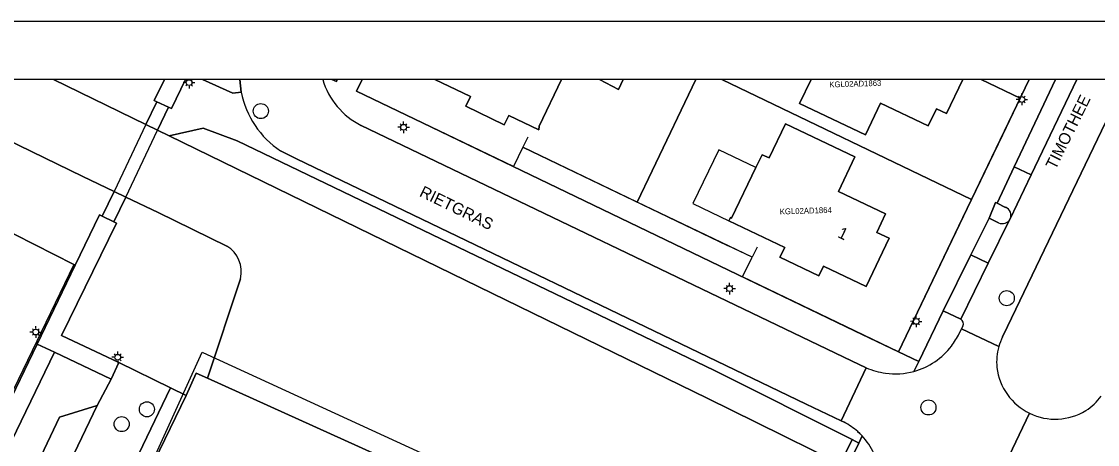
# Model space of a CAD drawing. Extents: x 124901 to 125496, y 515369 to 515789.
# Drawn here: x 125282.1 to 125375.1, y 515752.5 to 515789 of the extents above; entities that cross this region are included whole.
import ezdxf

# ---------------------------------------------------------------- set-up
doc = ezdxf.new("R2010")
doc.units = 0
for name, color, linetype in [('Alg Kaders', 7, 'Continuous'), ('Brug', 7, 'Continuous'), ('Gebouw', 7, 'Continuous'), ('Inrit', 7, 'Continuous'), ('Lichtmast', 7, 'Continuous'), ('Luifel', 7, 'Continuous'), ('Onbegroeid terrein', 7, 'Continuous'), ('Parkeren', 7, 'Continuous'), ('Perceelnummers', 7, 'Continuous'), ('Perceelsgrenzen', 7, 'Continuous'), ('Putten', 7, 'Continuous'), ('Scheiding', 7, 'Continuous'), ('Teksten', 7, 'Continuous'), ('Vegetatie', 7, 'Continuous'), ('Voetpad', 7, 'Continuous'), ('Water', 7, 'Continuous'), ('Wegen drempel verkeerseiland', 7, 'Continuous'), ('Wegen lokale weg', 7, 'Continuous')]:
    doc.layers.add(name, color=color, linetype=linetype)

msp = doc.modelspace()

# ---------------------------------------------------------------- linework, layer by layer
at = {"layer": 'Alg Kaders'}
for points in [[(125495.925, 515789.043), (124901.425, 515789.043), (124901.425, 515368.543), (125495.925, 515368.543)], [(125490.925, 515784.043), (124906.425, 515784.043), (124906.425, 515373.543), (125490.925, 515373.543)]]:
    msp.add_lwpolyline(points, close=True, dxfattribs=at)
at = {"layer": 'Brug'}
msp.add_lwpolyline([(125293.879, 515779.651), (125294.829, 515781.645), (125293.803, 515782.112), (125292.865, 515780.145), (125290.109, 515774.367), (125289.089, 515772.228), (125290.107, 515771.732), (125291.13, 515773.881)], close=True, dxfattribs=at)
at = {"layer": 'Gebouw'}
for points in [[(125317.842, 515784.043), (125320.92, 515782.562), (125320.517, 515781.727), (125323.845, 515780.121), (125324.236, 515780.932), (125326.83, 515779.681), (125326.87, 515779.994), (125328.804, 515784.043)], [(125332.081, 515784.043), (125333.723, 515783.185), (125334.133, 515784.043)], [(125350.364, 515784.043), (125349.378, 515781.976), (125355.073, 515779.259), (125356.377, 515781.992), (125360.503, 515780.023), (125361.212, 515781.51), (125362.085, 515781.093), (125363.492, 515784.043)]]:
    msp.add_lwpolyline(points, dxfattribs=at)
msp.add_lwpolyline([(125356.048, 515770.817), (125356.796, 515772.43), (125352.733, 515774.377), (125354.158, 515777.343), (125348.173, 515780.219), (125346.742, 515777.266), (125346.129, 515777.542), (125345.59, 515776.427), (125343.484, 515772.073), (125343.402, 515772.11), (125343.27, 515771.836), (125348.091, 515769.517), (125347.682, 515768.686), (125351.031, 515767.089), (125351.44, 515767.92), (125355.134, 515766.149), (125357.113, 515770.323)], close=True, dxfattribs=at)
at = {"layer": 'Inrit'}
for points in [[(125369.401, 515775.802), (125367.941, 515776.502), (125366.447, 515773.345), (125367.189, 515772.995)], [(125367.584, 515772.013), (125369.401, 515775.802)], [(125366.583, 515771.667), (125365.756, 515772.072), (125364.184, 515768.887), (125365.692, 515768.164), (125367.565, 515771.975)]]:
    msp.add_lwpolyline(points, dxfattribs=at)
msp.add_lwpolyline([(125284.154, 515762.61), (125283.465, 515761.184), (125284.966, 515760.475), (125289.873, 515758.156), (125290.539, 515759.585), (125285.579, 515761.938), (125290.327, 515771.625), (125290.107, 515771.732), (125289.089, 515772.228), (125288.843, 515772.348), (125286.753, 515768.008)], close=True, dxfattribs=at)
for centre, radius, start, end in [((125366.919, 515772.316), 0.731, 335.51236, 68.3116), ((125366.919, 515772.315), 0.73, 242.59479, 332.23282)]:
    msp.add_arc(centre, radius, start, end, dxfattribs=at)
at = {"layer": 'Lichtmast'}
for p, q in [((125296.299, 515783.768), (125296.099, 515783.767)), ((125296.387, 515783.979), (125296.324, 515784.043)), ((125296.811, 515783.979), (125296.874, 515784.043)), ((125296.899, 515783.767), (125297.099, 515783.767)), ((125296.387, 515783.555), (125296.315, 515783.484)), ((125296.599, 515783.467), (125296.599, 515783.267)), ((125296.811, 515783.555), (125296.881, 515783.484)), ((125368.589, 515782.613), (125368.589, 515782.813)), ((125368.289, 515782.314), (125368.089, 515782.313)), ((125368.377, 515782.101), (125368.305, 515782.03)), ((125368.377, 515782.525), (125368.307, 515782.596)), ((125368.589, 515782.013), (125368.589, 515781.813)), ((125368.801, 515782.525), (125368.872, 515782.597)), ((125368.801, 515782.101), (125368.871, 515782.03)), ((125368.889, 515782.313), (125369.089, 515782.313)), ((125314.929, 515780.121), (125314.859, 515780.192)), ((125315.141, 515780.209), (125315.141, 515780.409)), ((125315.353, 515780.121), (125315.424, 515780.193)), ((125314.841, 515779.91), (125314.641, 515779.909)), ((125314.929, 515779.697), (125314.857, 515779.626)), ((125315.141, 515779.609), (125315.141, 515779.409)), ((125315.353, 515779.697), (125315.423, 515779.626)), ((125315.441, 515779.909), (125315.641, 515779.909)), ((125343.116, 515766.185), (125343.046, 515766.256)), ((125343.328, 515766.273), (125343.328, 515766.473)), ((125343.54, 515766.185), (125343.611, 515766.257)), ((125343.028, 515765.974), (125342.828, 515765.973)), ((125343.116, 515765.761), (125343.044, 515765.69)), ((125343.328, 515765.673), (125343.328, 515765.473)), ((125343.54, 515765.761), (125343.61, 515765.69)), ((125343.628, 515765.973), (125343.828, 515765.973)), ((125359.247, 515763.36), (125359.177, 515763.431)), ((125359.459, 515763.448), (125359.459, 515763.648)), ((125359.671, 515763.36), (125359.742, 515763.432)), ((125283.131, 515762.438), (125283.061, 515762.509)), ((125283.343, 515762.526), (125283.343, 515762.726)), ((125283.555, 515762.438), (125283.626, 515762.51)), ((125359.159, 515763.149), (125358.959, 515763.148)), ((125359.247, 515762.936), (125359.175, 515762.865)), ((125359.459, 515762.848), (125359.459, 515762.648)), ((125359.671, 515762.936), (125359.741, 515762.865)), ((125359.759, 515763.148), (125359.959, 515763.148)), ((125283.043, 515762.227), (125282.843, 515762.226)), ((125283.131, 515762.014), (125283.059, 515761.943)), ((125283.343, 515761.926), (125283.343, 515761.726)), ((125283.555, 515762.014), (125283.625, 515761.943)), ((125283.643, 515762.226), (125283.843, 515762.226)), ((125290.431, 515760.346), (125290.431, 515760.546)), ((125290.131, 515760.047), (125289.931, 515760.046)), ((125290.219, 515759.834), (125290.147, 515759.763)), ((125290.219, 515760.258), (125290.149, 515760.329)), ((125290.431, 515759.746), (125290.431, 515759.546)), ((125290.643, 515760.258), (125290.714, 515760.33)), ((125290.643, 515759.834), (125290.713, 515759.763)), ((125290.731, 515760.046), (125290.931, 515760.046))]:
    msp.add_line(p, q, dxfattribs=at)
for centre in [(125296.599, 515783.767), (125368.589, 515782.313), (125315.141, 515779.909), (125343.328, 515765.973), (125359.459, 515763.148), (125283.343, 515762.226), (125290.431, 515760.046)]:
    msp.add_circle(centre, 0.25, dxfattribs=at)
at = {"layer": 'Luifel'}
msp.add_lwpolyline([(125345.59, 515776.427), (125342.382, 515777.968), (125340.143, 515773.339), (125343.27, 515771.836), (125343.402, 515772.11), (125343.484, 515772.073)], close=True, dxfattribs=at)
at = {"layer": 'Onbegroeid terrein'}
for points in [[(125311.561, 515784.043), (125311.077, 515783.036), (125316.78, 515780.288), (125354.115, 515762.337), (125357.936, 515760.516), (125363.147, 515771.4), (125369.237, 515784.043)], [(125328.804, 515784.043), (125326.87, 515779.994), (125326.83, 515779.681), (125324.236, 515780.932), (125323.845, 515780.121), (125320.517, 515781.727), (125320.92, 515782.562), (125317.842, 515784.043)], [(125334.133, 515784.043), (125333.723, 515783.185), (125332.081, 515784.043)], [(125363.492, 515784.043), (125362.085, 515781.093), (125361.212, 515781.51), (125360.503, 515780.023), (125356.377, 515781.992), (125355.073, 515779.259), (125349.378, 515781.976), (125350.364, 515784.043)], [(125312.784, 515751.645), (125298.192, 515758.231), (125297.217, 515758.671), (125296.354, 515756.747), (125282.093, 515727.334)]]:
    msp.add_lwpolyline(points, dxfattribs=at)
for points in [[(125292.865, 515780.145), (125293.879, 515779.651), (125294.829, 515781.645), (125293.803, 515782.112)], [(125356.796, 515772.43), (125356.048, 515770.817), (125357.113, 515770.323), (125355.134, 515766.149), (125351.44, 515767.92), (125351.031, 515767.089), (125347.682, 515768.686), (125348.091, 515769.517), (125343.27, 515771.836), (125343.402, 515772.11), (125343.484, 515772.073), (125345.59, 515776.427), (125346.129, 515777.542), (125346.742, 515777.266), (125348.173, 515780.219), (125354.158, 515777.343), (125352.733, 515774.377)], [(125291.13, 515773.881), (125290.109, 515774.367), (125289.089, 515772.228), (125290.107, 515771.732)]]:
    msp.add_lwpolyline(points, close=True, dxfattribs=at)
at = {"layer": 'Parkeren'}
msp.add_lwpolyline([(125371.51, 515784.043), (125367.941, 515776.502), (125369.401, 515775.802), (125373.352, 515784.043)], dxfattribs=at)
for points in [[(125363.315, 515763.33), (125365.692, 515768.164), (125364.184, 515768.887), (125361.797, 515764.051)], [(125288.661, 515755.872), (125285.386, 515754.86), (125281.698, 515747.095), (125281.57, 515746.821), (125274.483, 515731.631), (125275.344, 515729.477), (125275.615, 515728.799)]]:
    msp.add_lwpolyline(points, close=True, dxfattribs=at)
at = {"layer": 'Perceelsgrenzen'}
for points in [[(125340.417, 515784.043), (125336.625, 515776.14), (125335.335, 515773.453), (125325.45, 515778.192), (125324.631, 515776.515), (125311.077, 515783.036), (125311.561, 515784.043)], [(125369.237, 515784.043), (125368.46, 515782.431), (125366.921, 515779.235), (125364.239, 515773.667), (125363.862, 515772.884), (125357.936, 515760.516), (125352.652, 515763.04), (125344.446, 515766.986), (125345.285, 515768.683), (125335.335, 515773.453), (125325.45, 515778.192), (125324.631, 515776.515), (125311.077, 515783.036), (125311.561, 515784.043)], [(125342.645, 515784.043), (125364.239, 515773.667), (125363.862, 515772.884), (125357.936, 515760.516), (125352.652, 515763.04), (125344.446, 515766.986), (125345.285, 515768.683), (125335.335, 515773.453), (125336.625, 515776.14), (125340.417, 515784.043)], [(125365.071, 515784.043), (125368.46, 515782.431), (125366.921, 515779.235), (125364.239, 515773.667), (125342.645, 515784.043)], [(125369.237, 515784.043), (125368.46, 515782.431), (125365.071, 515784.043)]]:
    msp.add_lwpolyline(points, dxfattribs=at)
for points in [[(125273.267, 515709.056), (125277.174, 515717.127), (125281.038, 515725.109), (125284.871, 515733.051), (125288.88, 515741.36), (125289.394, 515742.417), (125291.305, 515746.353), (125297.742, 515760.474), (125298.15, 515760.28), (125322.355, 515749.172), (125344.52, 515739), (125346.795, 515737.956), (125340.276, 515724.697), (125338.174, 515720.359), (125336.97, 515717.875), (125334.47, 515712.696), (125332.165, 515707.919), (125329.819, 515703.059), (125327.473, 515698.198), (125325.136, 515693.355), (125321.468, 515685.754), (125308.957, 515691.825), (125298.065, 515697.077), (125289.1, 515701.4)], [(125289.394, 515742.417), (125291.305, 515746.353), (125297.742, 515760.474), (125298.15, 515760.28), (125322.355, 515749.172), (125314.143, 515731.981), (125313.524, 515730.704)]]:
    msp.add_lwpolyline(points, close=True, dxfattribs=at)
at = {"layer": 'Putten'}
for centre in [(125302.8, 515781.31), (125367.29, 515765.15), (125292.95, 515755.55), (125360.52, 515755.71), (125290.77, 515754.27)]:
    msp.add_circle(centre, 0.65, dxfattribs=at)
at = {"layer": 'Scheiding'}
for points in [[(125257.71, 515782.746), (125286.629, 515768.071)], [(125325.873, 515779.058), (125325.45, 515778.192), (125343.139, 515769.694)], [(125345.709, 515769.541), (125345.285, 515768.683), (125343.139, 515769.694)], [(125286.629, 515768.071), (125281.421, 515757.273)]]:
    msp.add_lwpolyline(points, dxfattribs=at)
msp.add_lwpolyline([(125352.897, 515750.85), (125345.865, 515736.317), (125346.002, 515736.243), (125346.389, 515736.034), (125354.493, 515752.637), (125353.913, 515752.949)], close=True, dxfattribs=at)
at = {"layer": 'Vegetatie'}
for points in [[(125245.727, 515784.043), (125243.821, 515778.135), (125242.665, 515775.667), (125242.599, 515775.509), (125251.929, 515770.819), (125251.979, 515770.923), (125257.71, 515782.746), (125286.629, 515768.071), (125286.753, 515768.008), (125288.843, 515772.348), (125289.089, 515772.228), (125290.109, 515774.367), (125287.419, 515775.649), (125278.512, 515779.968), (125271.268, 515784.043)], [(125284.865, 515784.043), (125292.865, 515780.145), (125293.803, 515782.112), (125293.584, 515782.212), (125294.473, 515784.043)], [(125296.294, 515784.043), (125295.08, 515781.531), (125294.829, 515781.645), (125293.879, 515779.651), (125294.863, 515779.172), (125297.824, 515779.828), (125300.759, 515778.747), (125342.016, 515758.912), (125353.913, 515752.949), (125354.493, 515752.637), (125354.78, 515753.257), (125354.593, 515753.447), (125354.398, 515753.629)], [(125301.105, 515782.944), (125300.374, 515782.844), (125297.754, 515784.043)], [(125308.935, 515784.043), (125309.329, 515783.872), (125309.407, 515784.043)], [(125377.598, 515784.043), (125367.35, 515762.716), (125366.907, 515761.798)], [(125353.223, 515754.435), (125352.959, 515754.561), (125349.949, 515756.003), (125305.892, 515777.184), (125304.499, 515777.871)], [(125299.851, 515769.651), (125293.937, 515772.544), (125291.13, 515773.881), (125290.107, 515771.732), (125290.327, 515771.625), (125285.579, 515761.938), (125290.539, 515759.585)], [(125367.189, 515772.995), (125366.447, 515773.345), (125366.305, 515773.421), (125365.756, 515772.072), (125366.583, 515771.667)], [(125367.565, 515771.975), (125367.584, 515772.013)], [(125290.539, 515759.585), (125294.998, 515757.409), (125296.354, 515756.747), (125297.217, 515758.671), (125298.192, 515758.231), (125301.033, 515766.831)], [(125363.315, 515763.33), (125361.797, 515764.051), (125359.676, 515759.673), (125359.267, 515758.829)], [(125363.181, 515762.09), (125363.371, 515762.493), (125363.487, 515762.739)]]:
    msp.add_lwpolyline(points, dxfattribs=at)
for points in [[(125286.629, 515768.071), (125257.71, 515782.746), (125251.979, 515770.923), (125253.753, 515769.95), (125241.257, 515744.095), (125253.422, 515738.216), (125255.56, 515742.647), (125252.045, 515744.402), (125254.307, 515749.089), (125257.831, 515747.387), (125261.08, 515754.095), (125276.44, 515746.646), (125283.465, 515761.184), (125284.154, 515762.61), (125286.753, 515768.008)], [(125275.615, 515728.799), (125275.344, 515729.477), (125274.483, 515731.631), (125281.57, 515746.821), (125281.698, 515747.095), (125285.386, 515754.86), (125288.661, 515755.872), (125289.873, 515758.156), (125284.966, 515760.475), (125272.159, 515734.076), (125268.062, 515725.6), (125268.777, 515725.42), (125269.164, 515725.351), (125270.088, 515725.317), (125271.12, 515725.395), (125271.975, 515725.619), (125273.146, 515726.148), (125273.784, 515726.591), (125274.019, 515726.754), (125274.716, 515727.37), (125275.164, 515727.991)]]:
    msp.add_lwpolyline(points, close=True, dxfattribs=at)
for centre, radius, start, end in [((125308.931, 515784.508), 7.981, 191.30113, 236.26646), ((125366.919, 515772.316), 0.731, 335.51236, 68.3116), ((125366.919, 515772.315), 0.73, 242.59479, 332.23282), ((125298.558, 515767.451), 2.552, 345.93327, 59.54862), ((125363.09, 515762.944), 0.447, 332.67655, 59.77684), ((125354.269, 515766.842), 10.1, 324.76996, 331.93173), ((125373.252, 515758.937), 6.961, 155.72775, 163.02389), ((125357.597, 515764.823), 6.222, 285.56505, 322.27734), ((125371.552, 515759.615), 5.138, 164.71984, 185.01165), ((125371.482, 515759.782), 5.086, 186.95813, 244.15006), ((125371.371, 515759.667), 5.047, 303.10021, 323.92348), ((125371.481, 515759.781), 5.085, 244.15013, 301.35959), ((125350.349, 515748.986), 6.161, 48.91115, 62.19192)]:
    msp.add_arc(centre, radius, start, end, dxfattribs=at)
at = {"layer": 'Voetpad'}
for points in [[(125294.473, 515784.043), (125293.584, 515782.212), (125293.803, 515782.112), (125294.829, 515781.645), (125295.08, 515781.531), (125296.294, 515784.043)], [(125297.754, 515784.043), (125300.374, 515782.844), (125301.105, 515782.944), (125300.99, 515784.043)], [(125309.407, 515784.043), (125309.329, 515783.872), (125308.935, 515784.043)], [(125359.267, 515758.829), (125359.676, 515759.673), (125357.936, 515760.516), (125354.115, 515762.337), (125316.78, 515780.288), (125311.077, 515783.036), (125311.561, 515784.043)], [(125369.237, 515784.043), (125363.147, 515771.4), (125357.936, 515760.516), (125359.676, 515759.673), (125361.797, 515764.051), (125364.184, 515768.887), (125365.756, 515772.072), (125366.305, 515773.421), (125366.447, 515773.345), (125367.941, 515776.502), (125371.51, 515784.043)], [(125311.485, 515780.063), (125353.863, 515759.747), (125355.142, 515759.131)], [(125282.093, 515727.334), (125296.354, 515756.747), (125294.998, 515757.409), (125282.013, 515730.394)], [(125354.78, 515753.257), (125354.493, 515752.637)], [(125354.493, 515752.637), (125346.389, 515736.034), (125346.002, 515736.243), (125340.408, 515724.765), (125324.335, 515691.583), (125321.576, 515685.879), (125321.172, 515685.045), (125317.348, 515683.674), (125315.366, 515683.99), (125314.34, 515682.195)]]:
    msp.add_lwpolyline(points, dxfattribs=at)
for points in [[(125292.865, 515780.145), (125290.109, 515774.367), (125289.089, 515772.228), (125290.107, 515771.732), (125291.13, 515773.881), (125293.879, 515779.651), (125294.829, 515781.645), (125293.803, 515782.112)], [(125254.307, 515749.089), (125252.045, 515744.402), (125255.56, 515742.647), (125253.422, 515738.216), (125241.257, 515744.095), (125240.295, 515741.95), (125267.236, 515729.001), (125266.108, 515726.489), (125266.201, 515726.444), (125266.319, 515726.387), (125267.285, 515725.952), (125268.062, 515725.6), (125272.159, 515734.076), (125284.966, 515760.475), (125283.465, 515761.184), (125276.44, 515746.646), (125261.08, 515754.095), (125257.831, 515747.387)]]:
    msp.add_lwpolyline(points, close=True, dxfattribs=at)
for centre, radius, start, end in [((125314.445, 515785.929), 6.571, 196.68361, 243.22528), ((125358.054, 515766.302), 7.74, 247.90222, 260.70846), ((125357.628, 515764.824), 6.215, 262.37778, 285.28743), ((125350.458, 515749.243), 5.898, 24.80715, 42.88172)]:
    msp.add_arc(centre, radius, start, end, dxfattribs=at)
at = {"layer": 'Water'}
for points in [[(125271.268, 515784.043), (125278.512, 515779.968), (125287.419, 515775.649), (125290.109, 515774.367), (125291.13, 515773.881), (125293.937, 515772.544), (125299.851, 515769.651)], [(125301.033, 515766.831), (125298.192, 515758.231), (125312.784, 515751.645), (125322.639, 515747.097), (125330.851, 515743.393), (125345.865, 515736.317), (125352.897, 515750.85), (125345.657, 515754.42), (125341.384, 515756.505), (125294.863, 515779.172), (125293.879, 515779.651), (125292.865, 515780.145), (125284.865, 515784.043)]]:
    msp.add_lwpolyline(points, dxfattribs=at)
msp.add_lwpolyline([(125352.897, 515750.85), (125353.913, 515752.949), (125342.016, 515758.912), (125300.759, 515778.747), (125297.824, 515779.828), (125294.863, 515779.172), (125341.384, 515756.505), (125345.657, 515754.42)], close=True, dxfattribs=at)
msp.add_arc((125298.558, 515767.451), 2.552, 345.93327, 59.54862, dxfattribs=at)
at = {"layer": 'Wegen drempel verkeerseiland'}
for points in [[(125366.595, 515760.969), (125363.371, 515762.493), (125363.181, 515762.09)], [(125355.142, 515759.131), (125352.959, 515754.561), (125353.223, 515754.435)], [(125369.264, 515755.205), (125364.806, 515745.927)], [(125364.806, 515745.927), (125369.264, 515755.205)], [(125354.398, 515753.629), (125354.593, 515753.447), (125354.78, 515753.257)]]:
    msp.add_lwpolyline(points, dxfattribs=at)
for centre, radius, start, end in [((125354.269, 515766.842), 10.1, 324.76996, 331.93173), ((125357.597, 515764.823), 6.222, 285.56505, 322.27734), ((125371.552, 515759.615), 5.138, 164.71984, 185.01165), ((125358.054, 515766.302), 7.74, 247.90222, 260.70846), ((125357.628, 515764.824), 6.215, 262.37778, 285.28743), ((125371.482, 515759.782), 5.086, 186.95813, 244.15006), ((125371.371, 515759.667), 5.047, 303.10021, 323.92348), ((125371.481, 515759.781), 5.085, 244.15013, 301.35959), ((125350.349, 515748.986), 6.161, 48.91115, 62.19192), ((125350.458, 515749.243), 5.898, 24.80715, 42.88172)]:
    msp.add_arc(centre, radius, start, end, dxfattribs=at)
at = {"layer": 'Wegen lokale weg'}
msp.add_line((125300.99, 515784.043), (125301.105, 515782.944), dxfattribs=at)
for points in [[(125373.352, 515784.043), (125369.401, 515775.802), (125367.584, 515772.013), (125367.565, 515771.975), (125365.692, 515768.164), (125363.315, 515763.33)], [(125366.907, 515761.798), (125367.35, 515762.716), (125377.598, 515784.043)], [(125304.499, 515777.871), (125305.892, 515777.184), (125349.949, 515756.003), (125352.959, 515754.561), (125355.142, 515759.131), (125353.863, 515759.747), (125311.485, 515780.063)], [(125363.487, 515762.739), (125363.371, 515762.493), (125366.595, 515760.969)], [(125282.013, 515730.394), (125294.998, 515757.409), (125290.539, 515759.585), (125289.873, 515758.156), (125288.661, 515755.872), (125275.615, 515728.799)]]:
    msp.add_lwpolyline(points, dxfattribs=at)
for centre, radius, start, end in [((125314.445, 515785.929), 6.571, 196.68361, 243.22528), ((125308.931, 515784.508), 7.981, 191.30113, 236.26646), ((125363.09, 515762.944), 0.447, 332.67655, 59.77684), ((125373.252, 515758.937), 6.961, 155.72775, 163.02389)]:
    msp.add_arc(centre, radius, start, end, dxfattribs=at)

# ---------------------------------------------------------------- texts
at = {"layer": 'Perceelnummers'}
for s, rotation, p in [('KGL02AD1863', 1.83217, (125351.955, 515783.347)), ('KGL02AD1864', 1.83212, (125347.671, 515772.379))]:
    msp.add_text(s, height=0.5, rotation=rotation, dxfattribs=at).set_placement(p)
at = {"layer": 'Teksten'}
for s, rotation, p in [('TIMOTHEE', 63.6, (125371.495, 515776.187)), ('RIETGRAS', 334, (125316.439, 515773.996)), ('1', 334.4, (125352.594, 515770.449))]:
    msp.add_text(s, height=1, rotation=rotation, dxfattribs=at).set_placement(p)

doc.saveas('drawing.dxf')
